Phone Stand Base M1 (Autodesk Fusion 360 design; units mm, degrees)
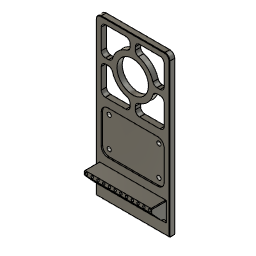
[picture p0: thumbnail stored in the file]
sketch "Sketch1" plane through (0, 0, 0) normal (0, 0, 1) x axis (1, 0, 0)
  line L1 (190.5, 0) -> (0, 0)
  line L2 (190.5, 88.9) -> (190.5, 0)
  line L3 (0, 88.9) -> (190.5, 88.9)
  line L4 (0, 0) -> (0, 88.9)
  point P1 (0, 0)
  point P2 (0, 0)
  point P3 (190.5, 0)
  point P5 (0, 88.9)
  horizontal L1
  vertical L2
  horizontal L3
  vertical L4
  coincident P1 P2
  dimension "d1" distance P2 P3 = 190.5
  dimension "d2" distance P2 P5 = 88.9
extrude "Extrude1" new body sketch "Sketch1" along normal blind 6.35
sketch "Sketch2" plane through (0, 0, 6.35) normal (0, 0, 1) x axis (-1, 0, 0)
  line L1 (0, 0) -> (0, -88.9)
  line L2 (-190.5, 0) -> (0, 0)
  line L3 (-190.5, -88.9) -> (-190.5, 0)
  line L4 (0, -88.9) -> (-190.5, -88.9)
  line L5 (-36.83, -85.09) -> (-19.05, -85.09)
  line L6 (-36.83, -3.81) -> (-36.83, -85.09)
  line L7 (-19.05, -3.81) -> (-36.83, -3.81)
  line L8 (-19.05, -85.09) -> (-19.05, -3.81)
  horizontal L5
  vertical L6
  horizontal L7
  vertical L8
  dimension "d5" distance L1 L8 = 19.05
  dimension "d6" distance L6 L8 = 17.78
  dimension "d7" distance L4 L5 = 3.81
  dimension "d8" distance L2 L7 = 3.81
extrude "Extrude2" add sketch "Sketch2" profile of L5 L6 L7 L8 along normal blind 17.78
fillet "Fillet1" radius 6
chamfer "Chamfer1" distance 12.7 distance 11.43
fillet "Fillet2" radius 6
chamfer "Chamfer2" distance 0.5 distance 0.508
fillet "Fillet4" radius 0.75
sketch "Sketch5" plane through (0, 0, 6.35) normal (0, 0, 1) x axis (-1, 0, 0)
  line L1 (-36.08, -85.09) -> (-13.05, -85.09)
  line L2 (-36.83, -4.56) -> (-36.83, -84.34)
  line L3 (-13.05, -3.81) -> (-36.08, -3.81)
  line L4 (-13.05, -85.09) -> (-13.05, -3.81)
  line L5 (-184.5, -0.5) -> (-0.5, -0.5)
  line L6 (-190, -82.9) -> (-190, -6)
  line L7 (-0.5, -88.4) -> (-184.5, -88.4)
  line L8 (-0.5, -0.5) -> (-0.5, -88.4)
  line L9 (0, -88.9) -> (-184.5, -88.9)
  line L10 (-190.5, -82.9) -> (-190.5, -6)
  line L11 (-184.15, -77.47) -> (-184.15, -52.705)
  line L12 (-154.305, -82.55) -> (-179.07, -82.55)
  line L13 (-184.15, -44.45) -> (-171.45, -44.45)
  line L14 (-190.5, -44.45) -> (-190, -44.45)
  line L15 (-179.07, -47.625) -> (-171.2508, -47.625)
  line L16 (-146.05, -82.55) -> (-146.05, -69.85)
  line L17 (-146.05, -88.9) -> (-146.05, -88.4)
  line L18 (-149.225, -77.47) -> (-149.225, -69.6508)
  line L19 (-149.225, -88.9) -> (-149.225, -88.4)
  arc A1 centre (-36.08, -84.34) radius 0.75 clockwise from (-36.08, -85.09) to (-36.83, -84.34)
  arc A2 centre (-36.08, -4.56) radius 0.75 clockwise from (-36.83, -4.56) to (-36.08, -3.81)
  arc A3 centre (-184.5, -6) radius 5.5 clockwise from (-190, -6) to (-184.5, -0.5)
  arc A4 centre (-184.5, -82.9) radius 5.5 clockwise from (-184.5, -88.4) to (-190, -82.9)
  circle C1 centre (-146.05, -44.45) radius 19.05
  circle C2 centre (-146.05, -44.45) radius 25.4
  arc A5 centre (-179.07, -77.47) radius 5.08 clockwise from (-179.07, -82.55) to (-184.15, -77.47)
  arc A6 centre (-154.305, -77.47) radius 5.08 clockwise from (-149.225, -77.47) to (-154.305, -82.55)
  arc A7 centre (-179.07, -52.705) radius 5.08 clockwise from (-184.15, -52.705) to (-179.07, -47.625)
  point P24 (-149.225, -69.6508)
  point P25 (-146.05, -69.85)
  point P26 (-171.2508, -47.625)
  point P27 (-171.45, -44.45)
  point P28 (-190.5, -44.45)
  point P29 (-184.15, -44.45)
  point P30 (-190, -44.45)
  point P31 (-146.05, -82.55)
  point P32 (-146.05, -88.4)
  point P33 (-149.225, -88.4)
  point P34 (-149.225, -88.9)
  point P35 (-146.05, -88.9)
  point P18 (-146.05, -44.45)
  coincident C2 P24
  coincident C2 P25
  coincident C2 P26
  coincident C2 P27
  coincident L10 P28
  coincident L11 P29
  coincident L6 P30
  collinear L13 L14
  coincident L12 P31
  coincident L7 P32
  collinear L16 L17
  coincident L7 P33
  collinear L18 L19
  coincident L9 P34
  coincident L9 P35
  tangent L12 A5
  tangent L11 A5
  tangent L18 A6
  tangent L12 A6
  tangent L11 A7
  tangent L15 A7
  dimension "d51" distance P18 L9 = 44.45
  dimension "d52" distance P18 L10 = 44.45
  dimension "d53" diameter C1 = 38.1
  dimension "d54" = 6.35
  dimension "d58" radius A5 = 5.08
  dimension "d59" radius A6 = 5.08
  dimension "d60" radius A7 = 5.08
extrude "Extrude5" cut sketch "Sketch5" profile of C1 C2 L19 L15 L11 L12 A5 A6 A7 no distance stored
fillet "Fillet5" radius 5
fillet "Fillet6" radius 5
circular_pattern "C-Pattern1" TotalAngle 360
fillet "Fillet7" radius 5
sketch "Sketch6" plane through (0, 0, 6.35) normal (0, 0, 1) x axis (-1, 0, 0)
  line L1 (-107.95, -77.47) -> (-107.95, -52.705)
  line L2 (-137.795, -82.55) -> (-113.03, -82.55)
  line L3 (-142.875, -73.7302) -> (-142.875, -77.47)
  line L4 (-113.03, -47.625) -> (-116.7698, -47.625)
  line L5 (-113.03, -6.35) -> (-137.795, -6.35)
  line L6 (-107.95, -36.195) -> (-107.95, -11.43)
  line L7 (-116.7698, -41.275) -> (-113.03, -41.275)
  line L8 (-142.875, -11.43) -> (-142.875, -15.1698)
  line L9 (-184.15, -11.43) -> (-184.15, -36.195)
  line L10 (-154.305, -6.35) -> (-179.07, -6.35)
  line L11 (-149.225, -15.1698) -> (-149.225, -11.43)
  line L12 (-179.07, -41.275) -> (-175.3302, -41.275)
  line L13 (-179.07, -82.55) -> (-154.305, -82.55)
  line L14 (-184.15, -52.705) -> (-184.15, -77.47)
  line L15 (-175.3302, -47.625) -> (-179.07, -47.625)
  line L16 (-149.225, -77.47) -> (-149.225, -73.7302)
  line L17 (-36.08, -85.09) -> (-13.05, -85.09)
  line L18 (-36.83, -4.56) -> (-36.83, -84.34)
  line L19 (-13.05, -3.81) -> (-36.08, -3.81)
  line L20 (-13.05, -85.09) -> (-13.05, -3.81)
  line L21 (-184.5, -0.5) -> (-0.5, -0.5)
  line L22 (-190, -82.9) -> (-190, -6)
  line L23 (-0.5, -88.4) -> (-184.5, -88.4)
  line L24 (-0.5, -0.5) -> (-0.5, -88.4)
  line L25 (-46.355, -82.55) -> (-98.425, -82.55)
  line L26 (-46.355, -6.35) -> (-46.355, -82.55)
  line L27 (-98.425, -6.35) -> (-46.355, -6.35)
  line L28 (-98.425, -82.55) -> (-98.425, -6.35)
  line L29 (0, -88.9) -> (-184.5, -88.9)
  arc A1 centre (-113.03, -52.705) radius 5.08 clockwise from (-113.03, -47.625) to (-107.95, -52.705)
  arc A2 centre (-113.03, -77.47) radius 5.08 clockwise from (-107.95, -77.47) to (-113.03, -82.55)
  arc A3 centre (-137.795, -77.47) radius 5.08 clockwise from (-137.795, -82.55) to (-142.875, -77.47)
  arc A4 centre (-137.875, -73.7302) radius 5 clockwise from (-142.875, -73.7302) to (-139.2196, -68.9144)
  arc A5 centre (-146.05, -44.45) radius 25.4 clockwise from (-121.5856, -51.2804) to (-139.2196, -68.9144)
  arc A6 centre (-116.7698, -52.625) radius 5 clockwise from (-121.5856, -51.2804) to (-116.7698, -47.625)
  arc A7 centre (-137.795, -11.43) radius 5.08 clockwise from (-142.875, -11.43) to (-137.795, -6.35)
  arc A8 centre (-113.03, -11.43) radius 5.08 clockwise from (-113.03, -6.35) to (-107.95, -11.43)
  arc A9 centre (-113.03, -36.195) radius 5.08 clockwise from (-107.95, -36.195) to (-113.03, -41.275)
  arc A10 centre (-116.7698, -36.275) radius 5 clockwise from (-116.7698, -41.275) to (-121.5856, -37.6196)
  arc A11 centre (-146.05, -44.45) radius 25.4 clockwise from (-139.2196, -19.9856) to (-121.5856, -37.6196)
  arc A12 centre (-137.875, -15.1698) radius 5 clockwise from (-139.2196, -19.9856) to (-142.875, -15.1698)
  arc A13 centre (-179.07, -36.195) radius 5.08 clockwise from (-179.07, -41.275) to (-184.15, -36.195)
  arc A14 centre (-179.07, -11.43) radius 5.08 clockwise from (-184.15, -11.43) to (-179.07, -6.35)
  arc A15 centre (-154.305, -11.43) radius 5.08 clockwise from (-154.305, -6.35) to (-149.225, -11.43)
  arc A16 centre (-154.225, -15.1698) radius 5 clockwise from (-149.225, -15.1698) to (-152.8804, -19.9856)
  arc A17 centre (-146.05, -44.45) radius 25.4 clockwise from (-170.5144, -37.6196) to (-152.8804, -19.9856)
  arc A18 centre (-175.3302, -36.275) radius 5 clockwise from (-170.5144, -37.6196) to (-175.3302, -41.275)
  arc A19 centre (-154.305, -77.47) radius 5.08 clockwise from (-149.225, -77.47) to (-154.305, -82.55)
  arc A20 centre (-179.07, -77.47) radius 5.08 clockwise from (-179.07, -82.55) to (-184.15, -77.47)
  arc A21 centre (-179.07, -52.705) radius 5.08 clockwise from (-184.15, -52.705) to (-179.07, -47.625)
  arc A22 centre (-175.3302, -52.625) radius 5 clockwise from (-175.3302, -47.625) to (-170.5144, -51.2804)
  arc A23 centre (-146.05, -44.45) radius 25.4 clockwise from (-152.8804, -68.9144) to (-170.5144, -51.2804)
  arc A24 centre (-154.225, -73.7302) radius 5 clockwise from (-152.8804, -68.9144) to (-149.225, -73.7302)
  circle C1 centre (-146.05, -44.45) radius 19.05
  arc A25 centre (-36.08, -84.34) radius 0.75 clockwise from (-36.08, -85.09) to (-36.83, -84.34)
  arc A26 centre (-36.08, -4.56) radius 0.75 clockwise from (-36.83, -4.56) to (-36.08, -3.81)
  arc A27 centre (-184.5, -6) radius 5.5 clockwise from (-190, -6) to (-184.5, -0.5)
  arc A28 centre (-184.5, -82.9) radius 5.5 clockwise from (-184.5, -88.4) to (-190, -82.9)
  horizontal L25
  vertical L26
  horizontal L27
  vertical L28
  dimension "d70" distance L25 L29 = 6.35
  dimension "d71" distance L25 L27 = 76.2
  dimension "d72" distance L6 L28 = 9.525
  dimension "d73" distance L18 L26 = 9.525
extrude "Extrude6" cut sketch "Sketch6" profile of L25 L26 L27 L28 against normal blind 1.6
fillet "Fillet8" radius 8
hole "Hole2" HoleDiameter 5.035 TipAngle 118
hole "Hole3" HoleDiameter 5.035 TipAngle 118
hole "Hole4" HoleDiameter 5.035 TipAngle 118
hole "Hole5" HoleDepth 30.48 HoleDiameter 5.035 TipAngle 118
hole "Hole6" HoleDepth 24.13 HoleDiameter 3 TipAngle 118 RefDim1 2.54 RefDim2 6.35
rectangular_pattern "R-Pattern2" countU 12 uSpaceDistance 76.2 vSpaceDistance 0
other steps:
thread "Thread2"
thread "Thread3"
thread "Thread4"
thread "Thread5"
